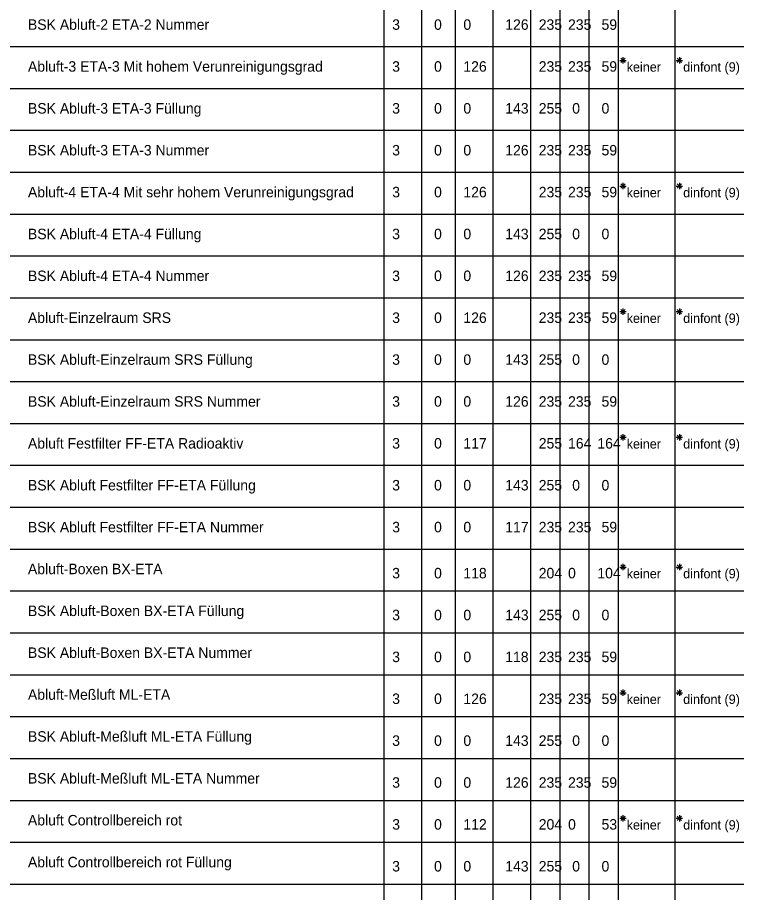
# Model space of a CAD drawing. Extents: x -26 to 55, y -9 to 161.
# Drawn here: x 16.25 to 33.54, y 76.8 to 97.69 of the extents above; entities that cross this region are included whole.
import ezdxf

# ---------------------------------------------------------------- set-up
doc = ezdxf.new("R2010")
doc.units = 0
doc.layers.add('Default', color=7, linetype='Continuous')

msp = doc.modelspace()

# ---------------------------------------------------------------- linework, layer by layer
at = {"layer": 'Default'}
for p, q in [((25, 147), (25, 0)), ((25.9, 146.3), (25.9, 28)), ((26.7, 146.3), (26.7, 28)), ((27.6, 146.3), (27.6, 28)), ((28.5, 146.3), (28.5, 28)), ((30.6, 146.3), (30.6, 28)), ((31.95, 146.3), (31.95, 28)), ((29.2, 145.5), (29.2, 28)), ((29.9, 145.5), (29.9, 28)), ((0, 97), (33.6, 97)), ((30.634, 96.67), (30.786, 96.67)), ((30.657, 96.723), (30.763, 96.617)), ((30.763, 96.723), (30.657, 96.617)), ((30.71, 96.746), (30.71, 96.594)), ((31.984, 96.67), (32.136, 96.67)), ((32.007, 96.723), (32.113, 96.617)), ((32.113, 96.723), (32.007, 96.617)), ((32.06, 96.746), (32.06, 96.594)), ((0, 96), (33.6, 96)), ((0, 95), (33.6, 95)), ((0, 94), (33.6, 94)), ((30.634, 93.67), (30.786, 93.67)), ((30.657, 93.723), (30.763, 93.617)), ((30.763, 93.723), (30.657, 93.617)), ((30.71, 93.746), (30.71, 93.594)), ((31.984, 93.67), (32.136, 93.67)), ((32.007, 93.723), (32.113, 93.617)), ((32.113, 93.723), (32.007, 93.617)), ((32.06, 93.746), (32.06, 93.594)), ((0, 93), (33.6, 93)), ((0, 92), (33.6, 92)), ((0, 91), (33.6, 91)), ((30.657, 90.723), (30.763, 90.617)), ((30.763, 90.723), (30.657, 90.617)), ((30.71, 90.746), (30.71, 90.594)), ((32.007, 90.723), (32.113, 90.617)), ((32.113, 90.723), (32.007, 90.617)), ((32.06, 90.746), (32.06, 90.594)), ((30.634, 90.67), (30.786, 90.67)), ((31.984, 90.67), (32.136, 90.67)), ((0, 90), (33.6, 90)), ((0, 89), (33.6, 89)), ((0, 88), (33.6, 88)), ((30.634, 87.67), (30.786, 87.67)), ((30.657, 87.723), (30.763, 87.617)), ((30.763, 87.723), (30.657, 87.617)), ((30.71, 87.746), (30.71, 87.594)), ((31.984, 87.67), (32.136, 87.67)), ((32.007, 87.723), (32.113, 87.617)), ((32.113, 87.723), (32.007, 87.617)), ((32.06, 87.746), (32.06, 87.594)), ((0, 87), (33.6, 87)), ((0, 86), (33.6, 86)), ((0, 85), (33.6, 85)), ((30.71, 84.646), (30.71, 84.494)), ((32.06, 84.646), (32.06, 84.494)), ((30.634, 84.57), (30.786, 84.57)), ((30.657, 84.623), (30.763, 84.517)), ((30.763, 84.623), (30.657, 84.517)), ((31.984, 84.57), (32.136, 84.57)), ((32.007, 84.623), (32.113, 84.517)), ((32.113, 84.623), (32.007, 84.517)), ((0, 84), (33.6, 84)), ((0, 83), (33.6, 83)), ((0, 82), (33.6, 82)), ((30.634, 81.57), (30.786, 81.57)), ((30.657, 81.623), (30.763, 81.517)), ((30.763, 81.623), (30.657, 81.517)), ((30.71, 81.646), (30.71, 81.494)), ((31.984, 81.57), (32.136, 81.57)), ((32.007, 81.623), (32.113, 81.517)), ((32.113, 81.623), (32.007, 81.517)), ((32.06, 81.646), (32.06, 81.494)), ((0, 81), (33.6, 81)), ((0, 80), (33.6, 80)), ((0, 78.997), (33.6, 78.997)), ((30.634, 78.57), (30.786, 78.57)), ((30.657, 78.623), (30.763, 78.517)), ((30.763, 78.623), (30.657, 78.517)), ((30.71, 78.646), (30.71, 78.494)), ((31.984, 78.57), (32.136, 78.57)), ((32.007, 78.623), (32.113, 78.517)), ((32.113, 78.623), (32.007, 78.517)), ((32.06, 78.646), (32.06, 78.494)), ((0, 78), (33.6, 78)), ((0, 77), (33.6, 77))]:
    msp.add_line(p, q, dxfattribs=at)

# ---------------------------------------------------------------- texts
for s, height, p in [('BSK Abluft-2 ETA-2 Nummer', 0.25, (16.5, 97.4)), ('3', 0.25, (25.2, 97.4)), ('0', 0.25, (26.2, 97.4)), ('0', 0.25, (26.9, 97.4)), ('126', 0.25, (27.9, 97.4)), ('235', 0.25, (28.7, 97.4)), ('235', 0.25, (29.4, 97.4)), ('59', 0.25, (30.2, 97.4)), ('Abluft-3 ETA-3 Mit hohem Verunreinigungsgrad', 0.25, (16.5, 96.4)), ('3', 0.25, (25.2, 96.4)), ('0', 0.25, (26.2, 96.4)), ('126', 0.25, (26.9, 96.4)), ('235', 0.25, (28.7, 96.4)), ('235', 0.25, (29.4, 96.4)), ('59', 0.25, (30.2, 96.4)), ('keiner', 0.225, (30.8, 96.4)), ('dinfont (9)', 0.225, (32.15, 96.4)), ('BSK Abluft-3 ETA-3 Füllung', 0.25, (16.5, 95.4)), ('3', 0.25, (25.2, 95.4)), ('0', 0.25, (26.2, 95.4)), ('0', 0.25, (26.9, 95.4)), ('143', 0.25, (27.9, 95.4)), ('255', 0.25, (28.7, 95.4)), ('0', 0.25, (29.5, 95.4)), ('0', 0.25, (30.2, 95.4)), ('BSK Abluft-3 ETA-3 Nummer', 0.25, (16.5, 94.4)), ('3', 0.25, (25.2, 94.4)), ('0', 0.25, (26.2, 94.4)), ('0', 0.25, (26.9, 94.4)), ('126', 0.25, (27.9, 94.4)), ('235', 0.25, (28.7, 94.4)), ('235', 0.25, (29.4, 94.4)), ('59', 0.25, (30.2, 94.4)), ('Abluft-4 ETA-4 Mit sehr hohem Verunreinigungsgrad', 0.25, (16.5, 93.4)), ('3', 0.25, (25.2, 93.4)), ('0', 0.25, (26.2, 93.4)), ('126', 0.25, (26.9, 93.4)), ('235', 0.25, (28.7, 93.4)), ('235', 0.25, (29.4, 93.4)), ('59', 0.25, (30.2, 93.4)), ('keiner', 0.225, (30.8, 93.4)), ('dinfont (9)', 0.225, (32.15, 93.4)), ('BSK Abluft-4 ETA-4 Füllung', 0.25, (16.5, 92.4)), ('3', 0.25, (25.2, 92.4)), ('0', 0.25, (26.2, 92.4)), ('0', 0.25, (26.9, 92.4)), ('143', 0.25, (27.9, 92.4)), ('255', 0.25, (28.7, 92.4)), ('0', 0.25, (29.5, 92.4)), ('0', 0.25, (30.2, 92.4)), ('BSK Abluft-4 ETA-4 Nummer', 0.25, (16.5, 91.4)), ('3', 0.25, (25.2, 91.4)), ('0', 0.25, (26.2, 91.4)), ('0', 0.25, (26.9, 91.4)), ('126', 0.25, (27.9, 91.4)), ('235', 0.25, (28.7, 91.4)), ('235', 0.25, (29.4, 91.4)), ('59', 0.25, (30.2, 91.4)), ('Abluft-Einzelraum SRS', 0.25, (16.5, 90.4)), ('3', 0.25, (25.2, 90.4)), ('0', 0.25, (26.2, 90.4)), ('126', 0.25, (26.9, 90.4)), ('235', 0.25, (28.7, 90.4)), ('235', 0.25, (29.4, 90.4)), ('59', 0.25, (30.2, 90.4)), ('keiner', 0.225, (30.8, 90.4)), ('dinfont (9)', 0.225, (32.15, 90.4)), ('BSK Abluft-Einzelraum SRS Füllung', 0.25, (16.5, 89.4)), ('3', 0.25, (25.2, 89.4)), ('0', 0.25, (26.2, 89.4)), ('0', 0.25, (26.9, 89.4)), ('143', 0.25, (27.9, 89.4)), ('255', 0.25, (28.7, 89.4)), ('0', 0.25, (29.5, 89.4)), ('0', 0.25, (30.2, 89.4)), ('BSK Abluft-Einzelraum SRS Nummer', 0.25, (16.5, 88.4)), ('3', 0.25, (25.2, 88.4)), ('0', 0.25, (26.2, 88.4)), ('0', 0.25, (26.9, 88.4)), ('126', 0.25, (27.9, 88.4)), ('235', 0.25, (28.7, 88.4)), ('235', 0.25, (29.4, 88.4)), ('59', 0.25, (30.2, 88.4)), ('Abluft Festfilter FF-ETA Radioaktiv ', 0.25, (16.5, 87.4)), ('3', 0.25, (25.2, 87.4)), ('0', 0.25, (26.2, 87.4)), ('117', 0.25, (26.9, 87.4)), ('255', 0.25, (28.7, 87.4)), ('164', 0.25, (29.4, 87.4)), ('164', 0.25, (30.1, 87.4)), ('keiner', 0.225, (30.8, 87.4)), ('dinfont (9)', 0.225, (32.15, 87.4)), ('BSK Abluft Festfilter FF-ETA Füllung', 0.25, (16.5, 86.4)), ('3', 0.25, (25.2, 86.4)), ('0', 0.25, (26.2, 86.4)), ('0', 0.25, (26.9, 86.4)), ('143', 0.25, (27.9, 86.4)), ('255', 0.25, (28.7, 86.4)), ('0', 0.25, (29.5, 86.4)), ('0', 0.25, (30.2, 86.4)), ('BSK Abluft Festfilter FF-ETA Nummer', 0.25, (16.5, 85.4)), ('3', 0.25, (25.2, 85.4)), ('0', 0.25, (26.2, 85.4)), ('0', 0.25, (26.9, 85.4)), ('117', 0.25, (27.9, 85.4)), ('235', 0.25, (28.7, 85.4)), ('235', 0.25, (29.4, 85.4)), ('59', 0.25, (30.2, 85.4)), ('Abluft-Boxen BX-ETA', 0.25, (16.5, 84.4)), ('3', 0.25, (25.2, 84.3)), ('0', 0.25, (26.2, 84.3)), ('118', 0.25, (26.9, 84.3)), ('204', 0.25, (28.7, 84.3)), ('0', 0.25, (29.4, 84.3)), ('104', 0.25, (30.1, 84.3)), ('keiner', 0.225, (30.8, 84.3)), ('dinfont (9)', 0.225, (32.15, 84.3)), ('BSK Abluft-Boxen BX-ETA Füllung', 0.25, (16.5, 83.4)), ('3', 0.25, (25.2, 83.3)), ('0', 0.25, (26.2, 83.3)), ('0', 0.25, (26.9, 83.3)), ('143', 0.25, (27.9, 83.3)), ('255', 0.25, (28.7, 83.3)), ('0', 0.25, (29.5, 83.3)), ('0', 0.25, (30.2, 83.3)), ('BSK Abluft-Boxen BX-ETA Nummer', 0.25, (16.5, 82.4)), ('3', 0.25, (25.2, 82.3)), ('0', 0.25, (26.2, 82.3)), ('0', 0.25, (26.9, 82.3)), ('118', 0.25, (27.9, 82.3)), ('235', 0.25, (28.7, 82.3)), ('235', 0.25, (29.4, 82.3)), ('59', 0.25, (30.2, 82.3)), ('Abluft-Meßluft ML-ETA', 0.25, (16.5, 81.4)), ('3', 0.25, (25.2, 81.3)), ('0', 0.25, (26.2, 81.3)), ('126', 0.25, (26.9, 81.3)), ('235', 0.25, (28.7, 81.3)), ('235', 0.25, (29.4, 81.3)), ('59', 0.25, (30.2, 81.3)), ('keiner', 0.225, (30.8, 81.3)), ('dinfont (9)', 0.225, (32.15, 81.3)), ('BSK Abluft-Meßluft ML-ETA Füllung', 0.25, (16.5, 80.4)), ('3', 0.25, (25.2, 80.3)), ('0', 0.25, (26.2, 80.3)), ('0', 0.25, (26.9, 80.3)), ('143', 0.25, (27.9, 80.3)), ('255', 0.25, (28.7, 80.3)), ('0', 0.25, (29.5, 80.3)), ('0', 0.25, (30.2, 80.3)), ('BSK Abluft-Meßluft ML-ETA Nummer', 0.25, (16.5, 79.4)), ('3', 0.25, (25.2, 79.3)), ('0', 0.25, (26.2, 79.3)), ('0', 0.25, (26.9, 79.3)), ('126', 0.25, (27.9, 79.3)), ('235', 0.25, (28.7, 79.3)), ('235', 0.25, (29.4, 79.3)), ('59', 0.25, (30.2, 79.3)), ('Abluft Controllbereich rot', 0.25, (16.5, 78.4)), ('3', 0.25, (25.2, 78.3)), ('0', 0.25, (26.2, 78.3)), ('112', 0.25, (26.9, 78.3)), ('204', 0.25, (28.7, 78.3)), ('0', 0.25, (29.4, 78.3)), ('53', 0.25, (30.2, 78.3)), ('keiner', 0.225, (30.8, 78.3)), ('dinfont (9)', 0.225, (32.15, 78.3)), ('Abluft Controllbereich rot Füllung', 0.25, (16.5, 77.4)), ('3', 0.25, (25.2, 77.3)), ('0', 0.25, (26.2, 77.3)), ('0', 0.25, (26.9, 77.3)), ('143', 0.25, (27.9, 77.3)), ('255', 0.25, (28.7, 77.3)), ('0', 0.25, (29.5, 77.3)), ('0', 0.25, (30.2, 77.3))]:
    msp.add_text(s, height=height, dxfattribs=at).set_placement(p)

doc.saveas('drawing.dxf')
